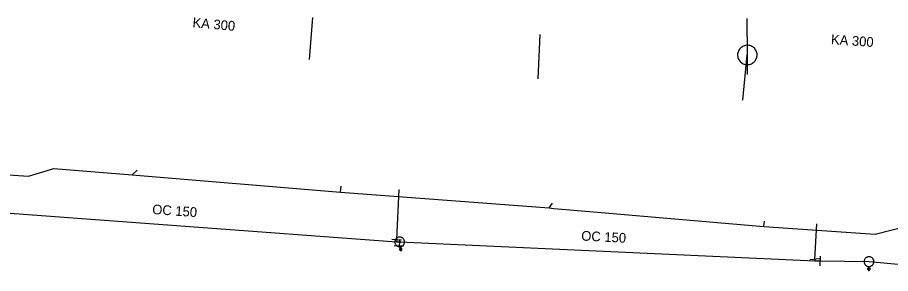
# Model space of a CAD drawing. Extents: x -759784 to -759434, y -974861 to -974639.
# Drawn here: x -759621.2 to -759531.4, y -974738.7 to -974712.3 of the extents above; entities that cross this region are included whole.
import ezdxf

# ---------------------------------------------------------------- set-up
doc = ezdxf.new("R2010")
doc.units = 0
for name, color, linetype in [('IS_CETIN_sdělovací kabel_podzemní', 7, 'Continuous'), ('IS_popis_ScVK', 7, 'Continuous'), ('IS_ScVK_Kanal', 7, 'Continuous'), ('IS_ScVK_Vodovod', 7, 'Continuous')]:
    doc.layers.add(name, color=color, linetype=linetype)

msp = doc.modelspace()

# ---------------------------------------------------------------- linework, layer by layer
at = {"layer": 'IS_CETIN_sdělovací kabel_podzemní'}
for points in [[(-759631.51, -974727.87), (-759620.07, -974728.63), (-759617.45, -974727.82), (-759609.42, -974728.47)], [(-759609.42, -974728.47), (-759608.91, -974728)], [(-759609.42, -974728.47), (-759587.97, -974730.28)], [(-759587.97, -974730.28), (-759587.93, -974729.66)], [(-759587.97, -974730.28), (-759566.53, -974731.9)], [(-759566.53, -974731.9), (-759566.2, -974731.39)], [(-759566.53, -974731.9), (-759566.06, -974731.94), (-759561.964, -974732.293)], [(-759561.964, -974732.293), (-759544.45, -974733.8)], [(-759544.45, -974733.8), (-759544.4, -974733.27)], [(-759544.45, -974733.8), (-759533, -974734.6), (-759529.66, -974733.73), (-759522.36, -974734.42)]]:
    msp.add_lwpolyline(points, dxfattribs=at)
at = {"layer": 'IS_ScVK_Kanal'}
for points in [[(-759591.162, -974716.614), (-759590.824, -974712.265)], [(-759546.149, -974716.134), (-759546.152, -974712.378)], [(-759567.669, -974718.591), (-759567.443, -974714.016)], [(-759545.149, -974716.134), (-759545.154, -974716.025), (-759545.172, -974715.917), (-759545.202, -974715.811), (-759545.242, -974715.71), (-759545.294, -974715.613), (-759545.356, -974715.523), (-759545.428, -974715.44), (-759545.508, -974715.366), (-759545.596, -974715.3), (-759545.69, -974715.245), (-759545.79, -974715.2), (-759545.895, -974715.167), (-759546.002, -974715.145), (-759546.111, -974715.135), (-759546.221, -974715.137), (-759546.329, -974715.151), (-759546.436, -974715.176), (-759546.539, -974715.213), (-759546.637, -974715.262), (-759546.729, -974715.32), (-759546.815, -974715.389), (-759546.892, -974715.466), (-759546.961, -974715.552), (-759547.02, -974715.644), (-759547.068, -974715.742), (-759547.105, -974715.845), (-759547.131, -974715.952), (-759547.145, -974716.06), (-759547.148, -974716.17), (-759547.138, -974716.279), (-759547.117, -974716.386), (-759547.083, -974716.49), (-759547.039, -974716.59), (-759546.984, -974716.685), (-759546.918, -974716.773), (-759546.844, -974716.853), (-759546.761, -974716.925), (-759546.671, -974716.987), (-759546.575, -974717.039), (-759546.473, -974717.08), (-759546.368, -974717.11), (-759546.26, -974717.128), (-759546.15, -974717.134), (-759546.041, -974717.128), (-759545.933, -974717.11), (-759545.828, -974717.081), (-759545.726, -974717.04), (-759545.629, -974716.988), (-759545.539, -974716.926), (-759545.456, -974716.855), (-759545.381, -974716.775), (-759545.316, -974716.687), (-759545.26, -974716.593), (-759545.216, -974716.493), (-759545.182, -974716.389), (-759545.16, -974716.281), (-759545.15, -974716.172), (-759545.149, -974716.134)], [(-759546.149, -974718.134), (-759546.148, -974715.134)], [(-759546.607, -974720.807), (-759546.15, -974716.134)], [(-759582.209, -974735.149), (-759582.234, -974735.394)], [(-759581.903, -974735.393), (-759581.958, -974735.819)], [(-759581.958, -974735.819), (-759581.789, -974736.158)], [(-759539.223, -974737.194), (-759539.225, -974737.362)]]:
    msp.add_lwpolyline(points, dxfattribs=at)
at = {"layer": 'IS_ScVK_Vodovod'}
for points in [[(-759582.209, -974735.149), (-759581.967, -974729.999)], [(-759626.999, -974732.058), (-759626.633, -974732.092), (-759582.234, -974735.394), (-759581.903, -974735.393)], [(-759539.223, -974737.194), (-759539, -974733.535)], [(-759582.708, -974735.126), (-759581.709, -974735.172)], [(-759581.413, -974735.292), (-759581.426, -974735.241), (-759581.445, -974735.192), (-759581.468, -974735.146), (-759581.496, -974735.101), (-759581.529, -974735.06), (-759581.566, -974735.023), (-759581.607, -974734.99), (-759581.65, -974734.962), (-759581.696, -974734.937), (-759581.745, -974734.918), (-759581.796, -974734.904), (-759581.848, -974734.896), (-759581.899, -974734.893), (-759581.952, -974734.895), (-759582.003, -974734.903), (-759582.054, -974734.916), (-759582.103, -974734.935), (-759582.15, -974734.959), (-759582.194, -974734.986), (-759582.235, -974735.019), (-759582.272, -974735.056), (-759582.305, -974735.097), (-759582.334, -974735.14), (-759582.359, -974735.186), (-759582.377, -974735.235), (-759582.391, -974735.286), (-759582.4, -974735.338), (-759582.402, -974735.389), (-759582.4, -974735.442), (-759582.392, -974735.493), (-759582.379, -974735.544), (-759582.36, -974735.593), (-759582.337, -974735.64), (-759582.309, -974735.684), (-759582.276, -974735.725), (-759582.24, -974735.762), (-759582.199, -974735.796), (-759582.156, -974735.824), (-759582.109, -974735.849), (-759582.06, -974735.867), (-759582.009, -974735.881), (-759581.958, -974735.89), (-759581.906, -974735.892), (-759581.853, -974735.89), (-759581.802, -974735.882), (-759581.751, -974735.869), (-759581.702, -974735.85), (-759581.656, -974735.828), (-759581.611, -974735.799), (-759581.57, -974735.766), (-759581.533, -974735.73), (-759581.5, -974735.689), (-759581.472, -974735.646), (-759581.447, -974735.599), (-759581.428, -974735.55), (-759581.414, -974735.499), (-759581.406, -974735.448), (-759581.403, -974735.396), (-759581.405, -974735.343), (-759581.413, -974735.292)], [(-759581.822, -974735.376), (-759581.824, -974735.367), (-759581.828, -974735.36), (-759581.831, -974735.352), (-759581.836, -974735.345), (-759581.841, -974735.338), (-759581.848, -974735.332), (-759581.854, -974735.326), (-759581.861, -974735.322), (-759581.869, -974735.318), (-759581.877, -974735.315), (-759581.885, -974735.312), (-759581.894, -974735.311), (-759581.902, -974735.311), (-759581.91, -974735.31), (-759581.919, -974735.312), (-759581.928, -974735.314), (-759581.935, -974735.318), (-759581.943, -974735.321), (-759581.95, -974735.326), (-759581.957, -974735.331), (-759581.963, -974735.338), (-759581.969, -974735.344), (-759581.973, -974735.351), (-759581.978, -974735.359), (-759581.98, -974735.367), (-759581.983, -974735.375), (-759581.984, -974735.384), (-759581.984, -974735.392), (-759581.985, -974735.4), (-759581.983, -974735.409), (-759581.981, -974735.418), (-759581.977, -974735.425), (-759581.974, -974735.433), (-759581.969, -974735.44), (-759581.964, -974735.447), (-759581.958, -974735.453), (-759581.951, -974735.459), (-759581.944, -974735.463), (-759581.936, -974735.468), (-759581.928, -974735.47), (-759581.92, -974735.473), (-759581.911, -974735.474), (-759581.903, -974735.474), (-759581.895, -974735.475), (-759581.886, -974735.473), (-759581.877, -974735.471), (-759581.87, -974735.467), (-759581.862, -974735.464), (-759581.855, -974735.459), (-759581.848, -974735.454), (-759581.842, -974735.448), (-759581.836, -974735.441), (-759581.832, -974735.434), (-759581.828, -974735.426), (-759581.825, -974735.418), (-759581.822, -974735.41), (-759581.821, -974735.401), (-759581.821, -974735.393), (-759581.82, -974735.385), (-759581.822, -974735.376)], [(-759581.458, -974735.8), (-759582.457, -974735.836)], [(-759581.915, -974736.158), (-759581.915, -974736.171), (-759581.913, -974736.184), (-759581.91, -974736.197), (-759581.905, -974736.209), (-759581.899, -974736.221), (-759581.892, -974736.232), (-759581.884, -974736.242), (-759581.874, -974736.252), (-759581.864, -974736.26), (-759581.853, -974736.267), (-759581.841, -974736.273), (-759581.829, -974736.278), (-759581.816, -974736.281), (-759581.803, -974736.283), (-759581.79, -974736.285), (-759581.777, -974736.284), (-759581.764, -974736.282), (-759581.751, -974736.279), (-759581.739, -974736.274), (-759581.727, -974736.268), (-759581.716, -974736.261), (-759581.706, -974736.253), (-759581.696, -974736.243), (-759581.688, -974736.233), (-759581.681, -974736.222), (-759581.675, -974736.21), (-759581.67, -974736.198), (-759581.667, -974736.185), (-759581.665, -974736.172), (-759581.663, -974736.159), (-759581.664, -974736.146), (-759581.666, -974736.133), (-759581.669, -974736.12), (-759581.674, -974736.108), (-759581.679, -974736.096), (-759581.687, -974736.085), (-759581.695, -974736.075), (-759581.705, -974736.065), (-759581.715, -974736.057), (-759581.726, -974736.05), (-759581.738, -974736.044), (-759581.75, -974736.039), (-759581.763, -974736.036), (-759581.776, -974736.034), (-759581.789, -974736.033), (-759581.802, -974736.033), (-759581.815, -974736.035), (-759581.828, -974736.038), (-759581.84, -974736.043), (-759581.852, -974736.049), (-759581.863, -974736.056), (-759581.873, -974736.064), (-759581.883, -974736.074), (-759581.891, -974736.084), (-759581.898, -974736.095), (-759581.904, -974736.107), (-759581.909, -974736.119), (-759581.912, -974736.132), (-759581.914, -974736.145), (-759581.915, -974736.158)], [(-759581.903, -974735.393), (-759539.225, -974737.362), (-759538.689, -974737.348)], [(-759581.895, -974736.158), (-759581.896, -974736.169), (-759581.894, -974736.18), (-759581.891, -974736.191), (-759581.887, -974736.201), (-759581.882, -974736.211), (-759581.876, -974736.22), (-759581.869, -974736.229), (-759581.861, -974736.237), (-759581.852, -974736.244), (-759581.843, -974736.25), (-759581.833, -974736.255), (-759581.823, -974736.259), (-759581.812, -974736.262), (-759581.801, -974736.265), (-759581.79, -974736.265), (-759581.779, -974736.265), (-759581.768, -974736.263), (-759581.757, -974736.26), (-759581.747, -974736.256), (-759581.737, -974736.251), (-759581.728, -974736.245), (-759581.719, -974736.238), (-759581.711, -974736.23), (-759581.704, -974736.221), (-759581.698, -974736.212), (-759581.693, -974736.202), (-759581.689, -974736.192), (-759581.686, -974736.181), (-759581.684, -974736.17), (-759581.683, -974736.159), (-759581.683, -974736.148), (-759581.684, -974736.137), (-759581.688, -974736.126), (-759581.692, -974736.116), (-759581.697, -974736.106), (-759581.703, -974736.097), (-759581.71, -974736.088), (-759581.718, -974736.08), (-759581.727, -974736.073), (-759581.736, -974736.067), (-759581.746, -974736.062), (-759581.755, -974736.058), (-759581.767, -974736.055), (-759581.777, -974736.053), (-759581.789, -974736.053), (-759581.8, -974736.052), (-759581.811, -974736.054), (-759581.822, -974736.057), (-759581.831, -974736.061), (-759581.842, -974736.066), (-759581.851, -974736.072), (-759581.86, -974736.079), (-759581.868, -974736.087), (-759581.875, -974736.096), (-759581.88, -974736.105), (-759581.886, -974736.115), (-759581.89, -974736.125), (-759581.893, -974736.136), (-759581.895, -974736.147), (-759581.895, -974736.158)], [(-759581.876, -974736.158), (-759581.876, -974736.167), (-759581.875, -974736.176), (-759581.872, -974736.185), (-759581.869, -974736.193), (-759581.865, -974736.201), (-759581.86, -974736.209), (-759581.853, -974736.216), (-759581.848, -974736.222), (-759581.841, -974736.228), (-759581.833, -974736.233), (-759581.825, -974736.237), (-759581.817, -974736.24), (-759581.808, -974736.243), (-759581.799, -974736.244), (-759581.79, -974736.246), (-759581.781, -974736.245), (-759581.772, -974736.244), (-759581.763, -974736.241), (-759581.755, -974736.238), (-759581.747, -974736.234), (-759581.739, -974736.229), (-759581.732, -974736.223), (-759581.726, -974736.217), (-759581.72, -974736.21), (-759581.715, -974736.202), (-759581.711, -974736.194), (-759581.708, -974736.186), (-759581.705, -974736.177), (-759581.704, -974736.168), (-759581.701, -974736.159), (-759581.703, -974736.15), (-759581.704, -974736.141), (-759581.706, -974736.132), (-759581.71, -974736.124), (-759581.714, -974736.116), (-759581.719, -974736.108), (-759581.725, -974736.101), (-759581.731, -974736.095), (-759581.738, -974736.089), (-759581.746, -974736.084), (-759581.754, -974736.08), (-759581.762, -974736.077), (-759581.771, -974736.074), (-759581.78, -974736.073), (-759581.789, -974736.072), (-759581.798, -974736.072), (-759581.807, -974736.073), (-759581.816, -974736.076), (-759581.824, -974736.079), (-759581.831, -974736.083), (-759581.84, -974736.088), (-759581.847, -974736.094), (-759581.853, -974736.1), (-759581.858, -974736.107), (-759581.864, -974736.115), (-759581.868, -974736.123), (-759581.871, -974736.131), (-759581.874, -974736.14), (-759581.875, -974736.149), (-759581.876, -974736.158)], [(-759581.856, -974736.158), (-759581.856, -974736.165), (-759581.855, -974736.172), (-759581.853, -974736.179), (-759581.851, -974736.185), (-759581.848, -974736.191), (-759581.844, -974736.197), (-759581.84, -974736.203), (-759581.835, -974736.208), (-759581.829, -974736.212), (-759581.823, -974736.216), (-759581.817, -974736.219), (-759581.811, -974736.222), (-759581.804, -974736.223), (-759581.797, -974736.226), (-759581.79, -974736.226), (-759581.782, -974736.226), (-759581.776, -974736.224), (-759581.769, -974736.223), (-759581.763, -974736.22), (-759581.755, -974736.217), (-759581.751, -974736.213), (-759581.745, -974736.209), (-759581.74, -974736.204), (-759581.736, -974736.198), (-759581.732, -974736.192), (-759581.728, -974736.186), (-759581.726, -974736.18), (-759581.724, -974736.173), (-759581.723, -974736.166), (-759581.722, -974736.159), (-759581.722, -974736.152), (-759581.723, -974736.145), (-759581.725, -974736.138), (-759581.728, -974736.132), (-759581.731, -974736.125), (-759581.735, -974736.12), (-759581.739, -974736.114), (-759581.744, -974736.109), (-759581.75, -974736.105), (-759581.755, -974736.101), (-759581.762, -974736.098), (-759581.768, -974736.095), (-759581.775, -974736.093), (-759581.782, -974736.092), (-759581.789, -974736.092), (-759581.796, -974736.092), (-759581.803, -974736.092), (-759581.809, -974736.094), (-759581.816, -974736.097), (-759581.822, -974736.1), (-759581.828, -974736.104), (-759581.834, -974736.108), (-759581.839, -974736.113), (-759581.843, -974736.119), (-759581.847, -974736.124), (-759581.85, -974736.131), (-759581.853, -974736.137), (-759581.853, -974736.144), (-759581.856, -974736.151), (-759581.856, -974736.158)], [(-759581.836, -974736.158), (-759581.836, -974736.163), (-759581.836, -974736.168), (-759581.835, -974736.173), (-759581.833, -974736.177), (-759581.831, -974736.182), (-759581.828, -974736.186), (-759581.825, -974736.189), (-759581.821, -974736.193), (-759581.818, -974736.196), (-759581.814, -974736.199), (-759581.809, -974736.201), (-759581.804, -974736.203), (-759581.8, -974736.204), (-759581.795, -974736.206), (-759581.79, -974736.206), (-759581.785, -974736.206), (-759581.78, -974736.205), (-759581.775, -974736.204), (-759581.771, -974736.202), (-759581.766, -974736.2), (-759581.762, -974736.197), (-759581.758, -974736.194), (-759581.755, -974736.19), (-759581.752, -974736.187), (-759581.749, -974736.183), (-759581.747, -974736.178), (-759581.745, -974736.174), (-759581.744, -974736.169), (-759581.743, -974736.164), (-759581.742, -974736.159), (-759581.742, -974736.154), (-759581.743, -974736.149), (-759581.744, -974736.144), (-759581.746, -974736.14), (-759581.748, -974736.135), (-759581.751, -974736.131), (-759581.754, -974736.127), (-759581.757, -974736.124), (-759581.761, -974736.121), (-759581.765, -974736.118), (-759581.77, -974736.116), (-759581.774, -974736.114), (-759581.779, -974736.113), (-759581.784, -974736.112), (-759581.789, -974736.112), (-759581.794, -974736.112), (-759581.799, -974736.113), (-759581.804, -974736.113), (-759581.808, -974736.115), (-759581.813, -974736.117), (-759581.817, -974736.12), (-759581.82, -974736.123), (-759581.824, -974736.126), (-759581.826, -974736.13), (-759581.83, -974736.134), (-759581.831, -974736.139), (-759581.834, -974736.143), (-759581.835, -974736.148), (-759581.836, -974736.153), (-759581.836, -974736.158)], [(-759581.816, -974736.158), (-759581.816, -974736.161), (-759581.817, -974736.164), (-759581.816, -974736.166), (-759581.815, -974736.169), (-759581.814, -974736.172), (-759581.812, -974736.174), (-759581.809, -974736.176), (-759581.808, -974736.178), (-759581.806, -974736.18), (-759581.804, -974736.182), (-759581.801, -974736.184), (-759581.798, -974736.185), (-759581.796, -974736.185), (-759581.793, -974736.186), (-759581.79, -974736.186), (-759581.787, -974736.186), (-759581.784, -974736.186), (-759581.781, -974736.185), (-759581.779, -974736.184), (-759581.776, -974736.183), (-759581.774, -974736.181), (-759581.771, -974736.179), (-759581.769, -974736.177), (-759581.768, -974736.175), (-759581.766, -974736.173), (-759581.765, -974736.17), (-759581.763, -974736.167), (-759581.763, -974736.165), (-759581.762, -974736.162), (-759581.761, -974736.159), (-759581.762, -974736.156), (-759581.762, -974736.153), (-759581.763, -974736.15), (-759581.764, -974736.148), (-759581.765, -974736.145), (-759581.767, -974736.143), (-759581.768, -974736.14), (-759581.77, -974736.138), (-759581.773, -974736.137), (-759581.775, -974736.135), (-759581.777, -974736.134), (-759581.78, -974736.133), (-759581.782, -974736.132), (-759581.786, -974736.132), (-759581.789, -974736.131), (-759581.792, -974736.132), (-759581.795, -974736.131), (-759581.797, -974736.133), (-759581.8, -974736.133), (-759581.803, -974736.134), (-759581.804, -974736.136), (-759581.807, -974736.137), (-759581.809, -974736.139), (-759581.811, -974736.142), (-759581.813, -974736.144), (-759581.814, -974736.147), (-759581.815, -974736.149), (-759581.816, -974736.152), (-759581.816, -974736.155), (-759581.816, -974736.158)], [(-759581.797, -974736.158), (-759581.797, -974736.16), (-759581.797, -974736.16), (-759581.796, -974736.16), (-759581.796, -974736.162), (-759581.797, -974736.163), (-759581.795, -974736.163), (-759581.795, -974736.163), (-759581.795, -974736.165), (-759581.795, -974736.165), (-759581.794, -974736.166), (-759581.792, -974736.166), (-759581.792, -974736.166), (-759581.792, -974736.167), (-759581.79, -974736.167), (-759581.79, -974736.167), (-759581.789, -974736.167), (-759581.788, -974736.167), (-759581.788, -974736.166), (-759581.787, -974736.166), (-759581.785, -974736.166), (-759581.785, -974736.165), (-759581.785, -974736.165), (-759581.784, -974736.164), (-759581.784, -974736.164), (-759581.782, -974736.163), (-759581.782, -974736.162), (-759581.781, -974736.161), (-759581.781, -974736.161), (-759581.781, -974736.16), (-759581.781, -974736.159), (-759581.781, -974736.158), (-759581.781, -974736.157), (-759581.781, -974736.157), (-759581.782, -974736.156), (-759581.782, -974736.155), (-759581.782, -974736.154), (-759581.782, -974736.154), (-759581.784, -974736.153), (-759581.784, -974736.153), (-759581.785, -974736.152), (-759581.786, -974736.152), (-759581.787, -974736.151), (-759581.787, -974736.151), (-759581.788, -974736.151), (-759581.789, -974736.151), (-759581.79, -974736.151), (-759581.791, -974736.151), (-759581.791, -974736.151), (-759581.792, -974736.152), (-759581.793, -974736.151), (-759581.794, -974736.153), (-759581.794, -974736.153), (-759581.795, -974736.153), (-759581.795, -974736.153), (-759581.796, -974736.155), (-759581.796, -974736.156), (-759581.796, -974736.157), (-759581.797, -974736.157), (-759581.797, -974736.158), (-759581.797, -974736.158)], [(-759538.667, -974736.848), (-759538.711, -974737.847)], [(-759534.138, -974737.41), (-759534.136, -974737.462), (-759534.131, -974737.514), (-759534.12, -974737.565), (-759534.103, -974737.615), (-759534.081, -974737.663), (-759534.053, -974737.707), (-759534.021, -974737.748), (-759533.986, -974737.788), (-759533.947, -974737.822), (-759533.904, -974737.852), (-759533.858, -974737.878), (-759533.809, -974737.897), (-759533.761, -974737.914), (-759533.708, -974737.924), (-759533.656, -974737.928), (-759533.605, -974737.926), (-759533.553, -974737.921), (-759533.501, -974737.909), (-759533.453, -974737.893), (-759533.405, -974737.871), (-759533.36, -974737.843), (-759533.317, -974737.813), (-759533.278, -974737.776), (-759533.245, -974737.738), (-759533.214, -974737.695), (-759533.189, -974737.649), (-759533.169, -974737.601), (-759533.154, -974737.551), (-759533.143, -974737.5), (-759533.138, -974737.447), (-759533.14, -974737.396), (-759533.145, -974737.343), (-759533.156, -974737.292), (-759533.173, -974737.243), (-759533.196, -974737.195), (-759533.222, -974737.15), (-759533.254, -974737.108), (-759533.289, -974737.07), (-759533.329, -974737.036), (-759533.372, -974737.005), (-759533.418, -974736.979), (-759533.465, -974736.959), (-759533.516, -974736.944), (-759533.568, -974736.934), (-759533.62, -974736.929), (-759533.672, -974736.931), (-759533.723, -974736.937), (-759533.775, -974736.948), (-759533.824, -974736.964), (-759533.872, -974736.987), (-759533.916, -974737.013), (-759533.957, -974737.044), (-759533.995, -974737.08), (-759534.032, -974737.119), (-759534.062, -974737.162), (-759534.087, -974737.208), (-759534.107, -974737.256), (-759534.122, -974737.307), (-759534.134, -974737.358), (-759534.138, -974737.41)], [(-759538.724, -974737.155), (-759539.721, -974737.231)], [(-759538.689, -974737.348), (-759533.638, -974737.429)], [(-759533.67, -974738.385), (-759533.652, -974737.92)], [(-759533.638, -974737.429), (-759520.172, -974738.658)], [(-759533.496, -974738.144), (-759533.826, -974738.131)], [(-759533.826, -974738.131), (-759533.67, -974738.385)], [(-759533.511, -974738.166), (-759533.811, -974738.154)], [(-759533.529, -974738.194), (-759533.796, -974738.183)], [(-759533.549, -974738.216), (-759533.777, -974738.207)], [(-759533.567, -974738.238), (-759533.763, -974738.232)], [(-759533.583, -974738.262), (-759533.749, -974738.257)], [(-759533.6, -974738.289), (-759533.734, -974738.283)], [(-759533.617, -974738.312), (-759533.718, -974738.309)], [(-759533.637, -974738.335), (-759533.701, -974738.333)], [(-759533.653, -974738.362), (-759533.685, -974738.36)], [(-759533.67, -974738.385), (-759533.496, -974738.144)], [(-759533.496, -974738.144), (-759533.661, -974738.137)]]:
    msp.add_lwpolyline(points, dxfattribs=at)

# ---------------------------------------------------------------- texts
at = {"layer": 'IS_popis_ScVK'}
for s, rotation, p in [('KA 300', 355, (-759603.233, -974713.273)), ('KA 300', 356, (-759537.573, -974715.01)), ('OC 150', 356, (-759607.37, -974732.521)), ('OC 150', 357, (-759563.248, -974735.25))]:
    msp.add_text(s, height=1, rotation=rotation, dxfattribs=at).set_placement(p)

doc.saveas('drawing.dxf')
